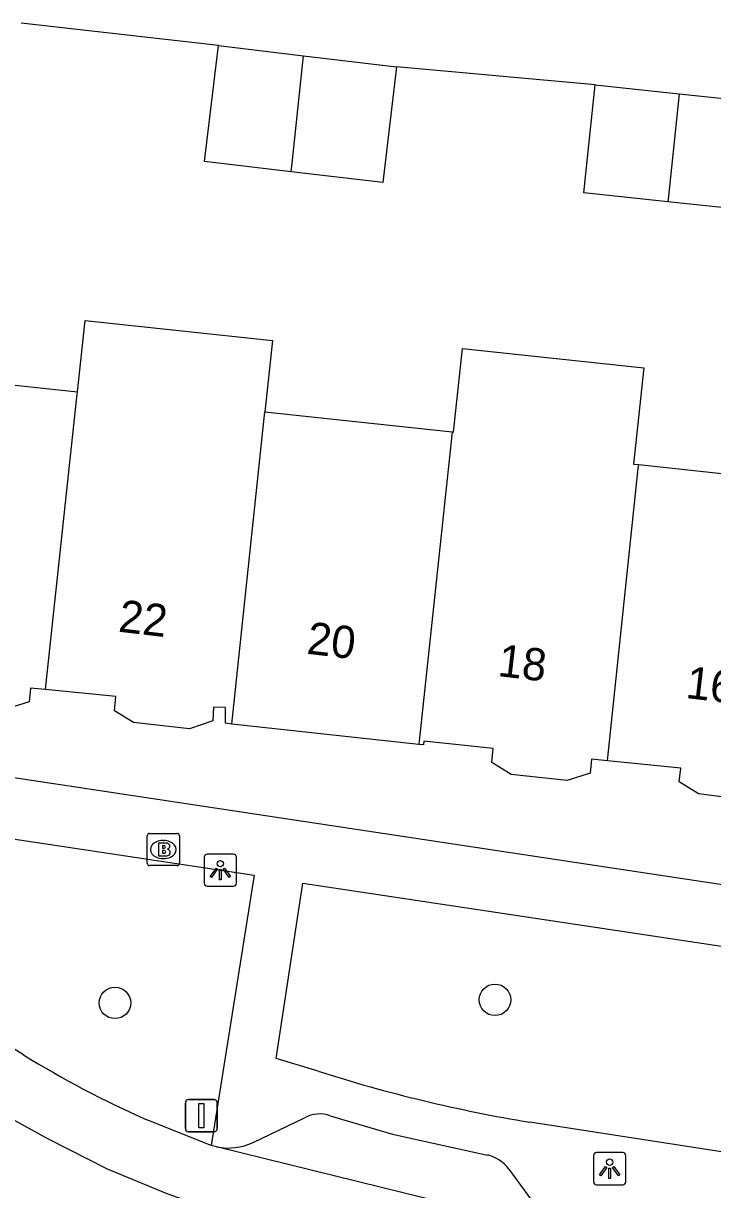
# Model space of a CAD drawing. Extents: x 163010 to 163853, y 382793 to 383982.
# Drawn here: x 163269.25 to 163290.62, y 383261.31 to 383297.49 of the extents above; entities that cross this region are included whole.
import ezdxf

# ---------------------------------------------------------------- set-up
doc = ezdxf.new("R2010")
doc.units = 0
for name, color, linetype in [('IMGEO_Boom', 7, 'Continuous'), ('IMGEO_Brandkraan', 7, 'Continuous'), ('IMGEO_Lichtpunt', 7, 'Continuous'), ('IMGEO_Pand', 7, 'Continuous'), ('IMGEO_Pand_nummerreeks', 7, 'Continuous'), ('IMGEO_Rijbaan_lokaal_gesloten', 7, 'Continuous'), ('IMGEO_Rijbaan_lokaal_open', 7, 'Continuous'), ('IMGEO_Verkeersbordpaal', 7, 'Continuous'), ('IMGEO_Voetpad_open', 7, 'Continuous')]:
    doc.layers.add(name, color=color, linetype=linetype)

msp = doc.modelspace()

# ---------------------------------------------------------------- linework, layer by layer
at = {"layer": 'IMGEO_Boom'}
for centre in [(163272.088, 383267.107), (163283.873, 383267.202)]:
    msp.add_circle(centre, 0.489, dxfattribs=at)
at = {"layer": 'IMGEO_Brandkraan'}
for p, q in [((163273.087, 383271.438), (163273.087, 383272.29)), ((163273.162, 383272.364), (163274.014, 383272.364)), ((163273.575, 383272.144), (163273.6, 383272.144)), ((163274.088, 383272.29), (163274.088, 383271.438)), ((163273.598, 383271.584), (163273.573, 383271.584)), ((163274.014, 383271.364), (163273.162, 383271.364))]:
    msp.add_line(p, q, dxfattribs=at)
for points in [[(163273.087, 383271.438), (163273.087, 383272.29)], [(163273.162, 383272.364), (163274.014, 383272.364)], [(163274.088, 383272.29), (163274.088, 383271.438)], [(163273.435, 383272.064), (163273.435, 383271.664), (163273.648, 383271.664)], [(163273.666, 383272.064), (163273.435, 383272.064)], [(163273.614, 383271.983), (163273.56, 383271.983), (163273.56, 383271.907)], [(163273.56, 383271.907), (163273.613, 383271.907)], [(163273.622, 383271.831), (163273.56, 383271.831), (163273.56, 383271.75)], [(163273.56, 383271.75), (163273.622, 383271.75)], [(163274.014, 383271.364), (163273.162, 383271.364)]]:
    msp.add_lwpolyline(points, dxfattribs=at)
for centre, radius, start, end in [((163273.164, 383272.288), 0.0765, 91.552, 178.448), ((163273.164, 383272.288), 0.0765, 91.552, 178.448), ((163274.012, 383272.288), 0.0765, 1.552, 88.448), ((163274.012, 383272.288), 0.0765, 1.552, 88.448), ((163273.615, 383271.945), 0.0379, 267.8285, 90.9355), ((163273.623, 383271.79), 0.0404, 269.8759, 90.5077), ((163273.67, 383271.919), 0.145, 59.4692, 91.5367), ((163273.695, 383271.966), 0.0922, 285.5137, 58.1501), ((163273.7, 383271.774), 0.105, 301.3115, 78.989), ((163273.164, 383271.44), 0.0765, 181.552, 268.448), ((163273.164, 383271.44), 0.0765, 181.552, 268.448), ((163273.654, 383271.915), 0.251, 268.6676, 293.5347), ((163274.012, 383271.44), 0.0765, 271.552, 358.448), ((163274.012, 383271.44), 0.0765, 271.552, 358.448)]:
    msp.add_arc(centre, radius, start, end, dxfattribs=at)
for centre, major_axis, ratio, start_param, end_param in [((163273.574, 383271.864), (-0.387, 0.002), 0.722429, 4.712389, 7.853982), ((163273.599, 383271.864), (-0.39, 0.002), 0.717154, 1.570796, 4.712389)]:
    msp.add_ellipse(centre, major_axis=major_axis, ratio=ratio, start_param=start_param, end_param=end_param, dxfattribs=at)
at = {"layer": 'IMGEO_Lichtpunt'}
for p, q in [((163274.859, 383271.627), (163274.859, 383270.82)), ((163274.859, 383271.627), (163274.859, 383270.82)), ((163275.761, 383271.722), (163274.953, 383271.722)), ((163275.761, 383271.722), (163274.953, 383271.722)), ((163275.855, 383270.82), (163275.855, 383271.627)), ((163275.855, 383270.82), (163275.855, 383271.627)), ((163274.953, 383270.726), (163275.761, 383270.726)), ((163274.953, 383270.726), (163275.761, 383270.726)), ((163286.93, 383262.367), (163286.93, 383261.56)), ((163286.93, 383262.367), (163286.93, 383261.56)), ((163287.832, 383262.462), (163287.024, 383262.462)), ((163287.832, 383262.462), (163287.024, 383262.462)), ((163287.926, 383261.56), (163287.926, 383262.367)), ((163287.926, 383261.56), (163287.926, 383262.367)), ((163287.024, 383261.466), (163287.832, 383261.466)), ((163287.024, 383261.466), (163287.832, 383261.466))]:
    msp.add_line(p, q, dxfattribs=at)
for points in [[(163275.233, 383271.291), (163275.272, 383271.263), (163275.084, 383271.001), (163275.046, 383271.028), (163275.233, 383271.291)], [(163275.335, 383271.243), (163275.382, 383271.243), (163275.382, 383270.921), (163275.335, 383270.921), (163275.335, 383271.243)], [(163275.445, 383271.263), (163275.483, 383271.29), (163275.67, 383271.028), (163275.631, 383271), (163275.445, 383271.263)], [(163287.304, 383262.031), (163287.343, 383262.003), (163287.155, 383261.741), (163287.117, 383261.768), (163287.304, 383262.031)], [(163287.406, 383261.983), (163287.453, 383261.983), (163287.453, 383261.661), (163287.406, 383261.661), (163287.406, 383261.983)], [(163287.516, 383262.003), (163287.554, 383262.03), (163287.741, 383261.768), (163287.702, 383261.74), (163287.516, 383262.003)]]:
    msp.add_lwpolyline(points, dxfattribs=at)
for centre in [(163275.358, 383271.425), (163287.429, 383262.165)]:
    msp.add_circle(centre, 0.0994, dxfattribs=at)
for centre, start, end in [((163274.953, 383271.627), 90, 180), ((163274.953, 383271.627), 90, 180), ((163275.761, 383271.627), 0, 90), ((163275.761, 383271.627), 0, 90), ((163274.953, 383270.82), 180, 270), ((163274.953, 383270.82), 180, 270), ((163275.761, 383270.82), 270, 0), ((163275.761, 383270.82), 270, 360), ((163287.024, 383262.367), 90, 180), ((163287.024, 383262.367), 90, 180), ((163287.832, 383262.367), 0, 90), ((163287.832, 383262.367), 0, 90), ((163287.024, 383261.56), 180, 270), ((163287.024, 383261.56), 180, 270), ((163287.832, 383261.56), 270, 0), ((163287.832, 383261.56), 270, 360)]:
    msp.add_arc(centre, 0.0946, start, end, dxfattribs=at)
at = {"layer": 'IMGEO_Pand'}
for points in [[(163277.556, 383292.892), (163274.871, 383293.211), (163275.298, 383296.803)], [(163275.298, 383296.803), (163277.934, 383296.49)], [(163277.556, 383292.892), (163277.595, 383293.245), (163277.934, 383296.49)], [(163277.934, 383296.49), (163280.822, 383296.147)], [(163280.822, 383296.147), (163280.396, 383292.555), (163277.556, 383292.892)], [(163289.233, 383291.959), (163286.623, 383292.234), (163286.977, 383295.585)], [(163286.977, 383295.585), (163289.585, 383295.31)], [(163289.585, 383295.31), (163289.24, 383292.026), (163289.233, 383291.959)], [(163289.585, 383295.31), (163292.537, 383294.998)], [(163292.537, 383294.998), (163292.183, 383291.647), (163289.233, 383291.959)], [(163270.928, 383286.063), (163271.166, 383288.275), (163276.979, 383287.65), (163276.741, 383285.44)], [(163282.546, 383284.817), (163282.583, 383284.813), (163282.862, 383287.411), (163288.484, 383286.808), (163288.164, 383283.822), (163288.328, 383283.804)], [(163265.114, 383286.687), (163270.928, 383286.063)], [(163269.936, 383276.828), (163269.947, 383276.932), (163270.911, 383285.902), (163270.928, 383286.063)], [(163275.712, 383275.758), (163276.741, 383285.44)], [(163276.741, 383285.44), (163282.546, 383284.817)], [(163282.546, 383284.817), (163282.505, 383284.429), (163281.525, 383275.228), (163281.514, 383275.125)], [(163287.358, 383274.619), (163287.369, 383274.721), (163288.315, 383283.682), (163288.328, 383283.804)], [(163288.328, 383283.804), (163294.142, 383283.18)], [(163269.936, 383276.828), (163269.466, 383276.875), (163269.433, 383276.447), (163268.703, 383276.217), (163266.967, 383276.401), (163266.374, 383276.777), (163266.404, 383277.233), (163264.123, 383277.438)], [(163275.712, 383275.758), (163275.521, 383275.779), (163275.521, 383276.272), (163275.149, 383276.279), (163275.129, 383275.857), (163274.405, 383275.612), (163272.669, 383275.809), (163272.071, 383276.17), (163272.119, 383276.609), (163269.936, 383276.828)], [(163281.514, 383275.125), (163275.712, 383275.758)], [(163287.358, 383274.619), (163286.87, 383274.668), (163286.82, 383274.238), (163286.107, 383274.005), (163284.375, 383274.188), (163283.772, 383274.564), (163283.815, 383274.998), (163281.663, 383275.224), (163281.657, 383275.109), (163281.514, 383275.125)], [(163293.162, 383274.003), (163292.678, 383274.057), (163292.631, 383273.625), (163291.949, 383273.367), (163290.184, 383273.591), (163289.584, 383273.961), (163289.634, 383274.392), (163287.358, 383274.619)]]:
    msp.add_lwpolyline(points, dxfattribs=at)
at = {"layer": 'IMGEO_Rijbaan_lokaal_gesloten'}
for points in [[(163259.805, 383267.54), (163261.871, 383267.087), (163264.002, 383266.241), (163265.531, 383265.482), (163268.17, 383263.899), (163269.993, 383262.898), (163271.849, 383261.958), (163273.697, 383261.198), (163275.426, 383260.58), (163277.327, 383260.004), (163279.243, 383259.481), (163281.431, 383259.01), (163285.184, 383258.317)], [(163269.249, 383265.496), (163267.87, 383266.342)], [(163275.071, 383262.681), (163273.077, 383263.483)], [(163275.24, 383262.639), (163275.071, 383262.681)], [(163285.467, 383260.115), (163275.24, 383262.639)]]:
    msp.add_lwpolyline(points, dxfattribs=at)
msp.add_arc((163285.893, 383292.5), 31.721, 238.3528, 246.1709, dxfattribs=at)
at = {"layer": 'IMGEO_Rijbaan_lokaal_open'}
for points in [[(163275.298, 383296.803), (163269.186, 383297.494)], [(163286.977, 383295.585), (163280.822, 383296.147)]]:
    msp.add_lwpolyline(points, dxfattribs=at)
at = {"layer": 'IMGEO_Verkeersbordpaal'}
for p, q in [((163274.272, 383263.209), (163274.272, 383264.009)), ((163274.272, 383264.009), (163274.272, 383263.209)), ((163274.372, 383264.109), (163275.162, 383264.109)), ((163275.162, 383264.109), (163274.372, 383264.109)), ((163275.262, 383264.009), (163275.262, 383263.209)), ((163275.262, 383263.209), (163275.262, 383264.009)), ((163275.162, 383263.109), (163274.372, 383263.109)), ((163274.372, 383263.109), (163275.162, 383263.109))]:
    msp.add_line(p, q, dxfattribs=at)
msp.add_lwpolyline([(163274.692, 383263.984), (163274.842, 383263.984), (163274.842, 383263.234), (163274.692, 383263.234), (163274.692, 383263.984)], dxfattribs=at)
for centre, start, end in [((163274.372, 383264.009), 90, 180), ((163274.372, 383264.009), 90, 180), ((163275.162, 383264.009), 0, 90), ((163275.162, 383264.009), 360, 90), ((163274.372, 383263.209), 180, 270), ((163274.372, 383263.209), 180, 270), ((163275.162, 383263.209), 270, 0), ((163275.162, 383263.209), 270, 0)]:
    msp.add_arc(centre, 0.1, start, end, dxfattribs=at)
at = {"layer": 'IMGEO_Voetpad_open'}
for points in [[(163253.685, 383276.401), (163334.658, 383264.168)], [(163247.775, 383272.392), (163248.12, 383275.325), (163255.531, 383274.209), (163276.404, 383271.065), (163275.071, 383262.681)], [(163278.395, 383264.986), (163277.086, 383265.386), (163277.911, 383270.821), (163300.992, 383267.346)], [(163300.992, 383267.346), (163299.981, 383261.077), (163284.957, 383263.403)], [(163276.37, 383262.777), (163277.966, 383263.542)], [(163278.766, 383263.605), (163280.695, 383263.036), (163283.639, 383262.388)], [(163284.298, 383261.946), (163285.284, 383260.601)]]:
    msp.add_lwpolyline(points, dxfattribs=at)
for centre, radius, start, end in [((163292.524, 383309.162), 46.38, 252.2641, 260.6104), ((163278.436, 383262.681), 0.981, 70.3662, 118.6393), ((163275.594, 383264.436), 1.832, 258.8611, 295.0644), ((163283.39, 383261.305), 1.112, 35.2373, 77.0621)]:
    msp.add_arc(centre, radius, start, end, dxfattribs=at)

# ---------------------------------------------------------------- texts
at = {"layer": 'IMGEO_Pand_nummerreeks'}
for s, rotation, p in [('22', 353.3284, (163272.171, 383278.625)), ('20', 353.3308, (163278.01, 383277.941)), ('18', 353.3308, (163283.932, 383277.248)), ('16', 353.3284, (163289.761, 383276.567))]:
    msp.add_text(s, height=1, rotation=rotation, dxfattribs=at).set_placement(p)

doc.saveas('drawing.dxf')
